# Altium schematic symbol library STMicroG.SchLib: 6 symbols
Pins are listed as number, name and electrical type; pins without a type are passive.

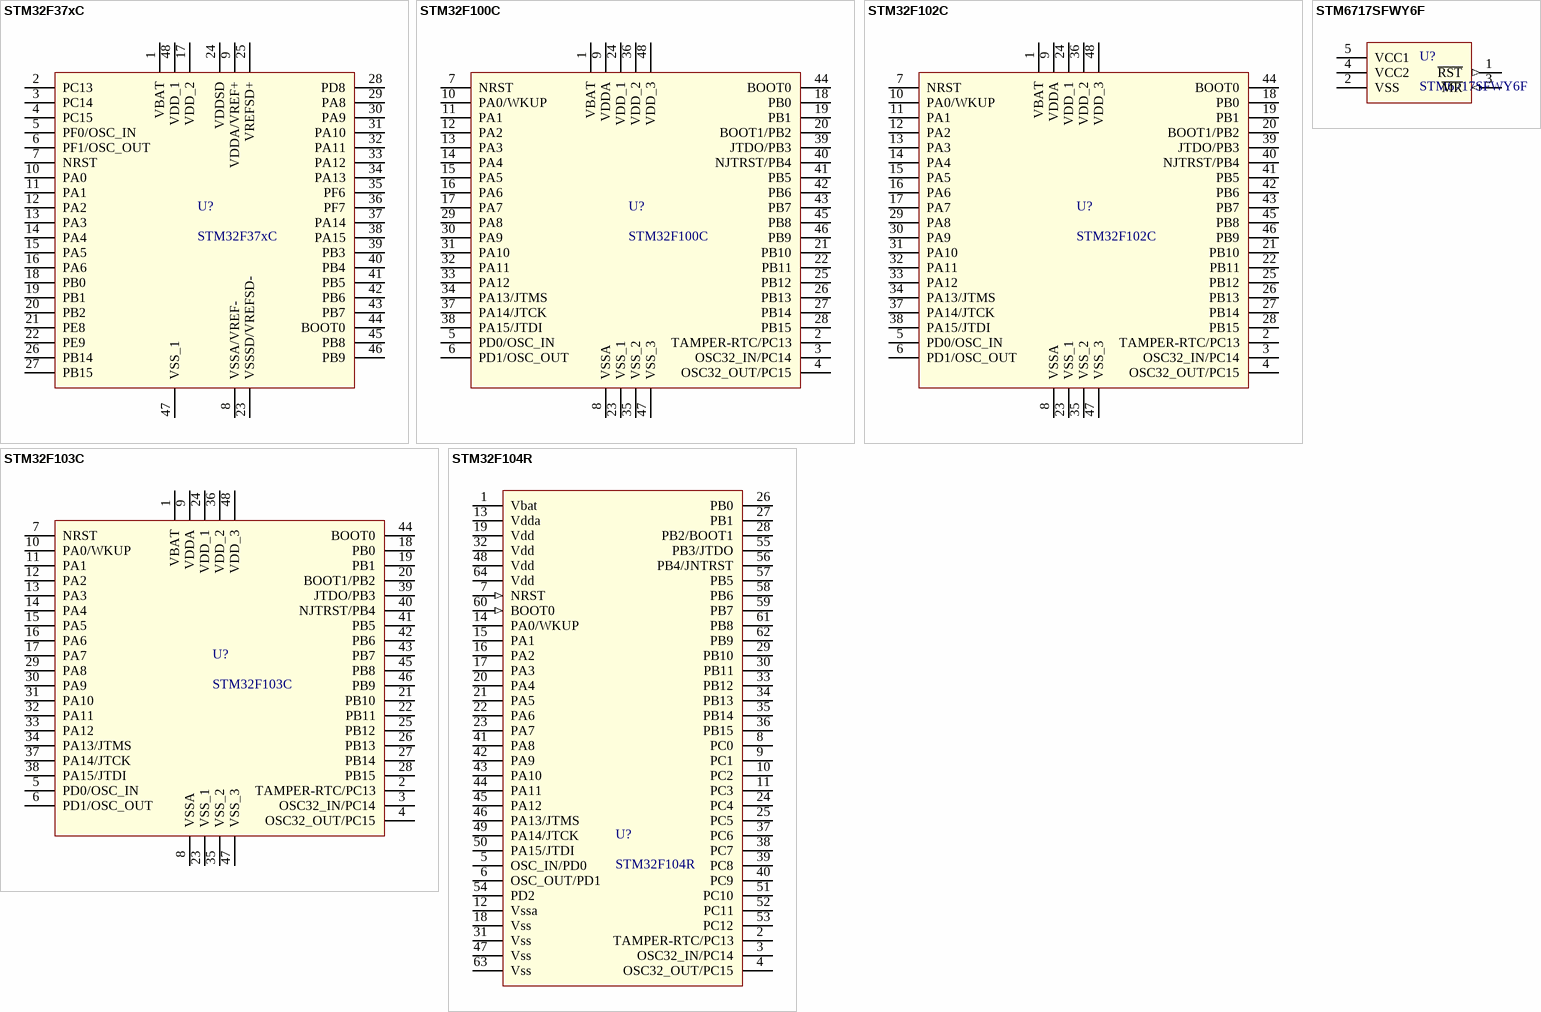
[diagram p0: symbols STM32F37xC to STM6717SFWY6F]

## STM32F37xC
designator U?
footprint SQFP50P900X900-48N (Shrink QFP, 48-Leads, Body 7x7mm, Pitch 0.5mm, IPC Medium Density)
pins: 1 VBAT, 2 PC13, 3 PC14, 4 PC15, 5 PF0/OSC_IN, 6 PF1/OSC_OUT, 7 NRST, 8 VSSA/VREF-, 9 VDDA/VREF+, 10 PA0, 11 PA1, 12 PA2, 13 PA3, 14 PA4, 15 PA5, 16 PA6, 17 VDD_2, 18 PB0, 19 PB1, 20 PB2, 21 PE8, 22 PE9, 23 VSSSD/VREFSD-, 24 VDDSD, 25 VREFSD+, 26 PB14, 27 PB15, 28 PD8, 29 PA8, 30 PA9, 31 PA10, 32 PA11, 33 PA12, 34 PA13, 35 PF6, 36 PF7, 37 PA14, 38 PA15, 39 PB3, 40 PB4, 41 PB5, 42 PB6, 43 PB7, 44 BOOT0, 45 PB8, 46 PB9, 47 VSS_1, 48 VDD_1

## STM32F100C
designator U?
footprint SQFP50P900X900-48N (Shrink QFP, 48-Leads, Body 7x7mm, Pitch 0.5mm, IPC Medium Density)
pins: 1 VBAT, 2 TAMPER-RTC/PC13, 3 OSC32_IN/PC14, 4 OSC32_OUT/PC15, 5 PD0/OSC_IN, 6 PD1/OSC_OUT, 7 NRST, 8 VSSA, 9 VDDA, 10 PA0/WKUP, 11 PA1, 12 PA2, 13 PA3, 14 PA4, 15 PA5, 16 PA6, 17 PA7, 18 PB0, 19 PB1, 20 BOOT1/PB2, 21 PB10, 22 PB11, 23 VSS_1, 24 VDD_1, 25 PB12, 26 PB13, 27 PB14, 28 PB15, 29 PA8, 30 PA9, 31 PA10, 32 PA11, 33 PA12, 34 PA13/JTMS, 35 VSS_2, 36 VDD_2, 37 PA14/JTCK, 38 PA15/JTDI, 39 JTDO/PB3, 40 NJTRST/PB4, 41 PB5, 42 PB6, 43 PB7, 44 BOOT0, 45 PB8, 46 PB9, 47 VSS_3, 48 VDD_3

## STM32F102C
designator U?
footprint SQFP50P900X900-48N (Shrink QFP, 48-Leads, Body 7x7mm, Pitch 0.5mm, IPC Medium Density)
pins: 1 VBAT, 2 TAMPER-RTC/PC13, 3 OSC32_IN/PC14, 4 OSC32_OUT/PC15, 5 PD0/OSC_IN, 6 PD1/OSC_OUT, 7 NRST, 8 VSSA, 9 VDDA, 10 PA0/WKUP, 11 PA1, 12 PA2, 13 PA3, 14 PA4, 15 PA5, 16 PA6, 17 PA7, 18 PB0, 19 PB1, 20 BOOT1/PB2, 21 PB10, 22 PB11, 23 VSS_1, 24 VDD_1, 25 PB12, 26 PB13, 27 PB14, 28 PB15, 29 PA8, 30 PA9, 31 PA10, 32 PA11, 33 PA12, 34 PA13/JTMS, 35 VSS_2, 36 VDD_2, 37 PA14/JTCK, 38 PA15/JTDI, 39 JTDO/PB3, 40 NJTRST/PB4, 41 PB5, 42 PB6, 43 PB7, 44 BOOT0, 45 PB8, 46 PB9, 47 VSS_3, 48 VDD_3

## STM32F103C
designator U?
footprint SQFP50P900X900-48N (Shrink QFP, 48-Leads, Body 7x7mm, Pitch 0.5mm, IPC Medium Density)
pins: 1 VBAT, 2 TAMPER-RTC/PC13, 3 OSC32_IN/PC14, 4 OSC32_OUT/PC15, 5 PD0/OSC_IN, 6 PD1/OSC_OUT, 7 NRST, 8 VSSA, 9 VDDA, 10 PA0/WKUP, 11 PA1, 12 PA2, 13 PA3, 14 PA4, 15 PA5, 16 PA6, 17 PA7, 18 PB0, 19 PB1, 20 BOOT1/PB2, 21 PB10, 22 PB11, 23 VSS_1, 24 VDD_1, 25 PB12, 26 PB13, 27 PB14, 28 PB15, 29 PA8, 30 PA9, 31 PA10, 32 PA11, 33 PA12, 34 PA13/JTMS, 35 VSS_2, 36 VDD_2, 37 PA14/JTCK, 38 PA15/JTDI, 39 JTDO/PB3, 40 NJTRST/PB4, 41 PB5, 42 PB6, 43 PB7, 44 BOOT0, 45 PB8, 46 PB9, 47 VSS_3, 48 VDD_3

## STM32F104R
designator U?
footprint SQFP50P1200X1200-64N (Shrink QFP, 64-Leads, Body 10x10mm, Pitch 0.5mm, IPC Medium Density)
pins: 1 Vbat (power), 2 TAMPER-RTC/PC13, 3 OSC32_IN/PC14, 4 OSC32_OUT/PC15, 5 OSC_IN/PD0, 6 OSC_OUT/PD1, 7 NRST (in), 8 PC0, 9 PC1, 10 PC2, 11 PC3, 12 Vssa (power), 13 Vdda (power), 14 PA0/WKUP, 15 PA1, 16 PA2, 17 PA3, 18 Vss (power), 19 Vdd (power), 20 PA4, 21 PA5, 22 PA6, 23 PA7, 24 PC4, 25 PC5, 26 PB0, 27 PB1, 28 PB2/BOOT1, 29 PB10, 30 PB11, 31 Vss (power), 32 Vdd (power), 33 PB12, 34 PB13, 35 PB14, 36 PB15, 37 PC6, 38 PC7, 39 PC8, 40 PC9, 41 PA8, 42 PA9, 43 PA10, 44 PA11, 45 PA12, 46 PA13/JTMS, 47 Vss (power), 48 Vdd (power), 49 PA14/JTCK, 50 PA15/JTDI, 51 PC10, 52 PC11, 53 PC12, 54 PD2, 55 PB3/JTDO, 56 PB4/JNTRST, 57 PB5, 58 PB6, 59 PB7, 60 BOOT0 (in), 61 PB8, 62 PB9, 63 Vss (power), 64 Vdd (power)

## STM6717SFWY6F
designator U?
Dual voltage supervisor with reset
pins: 1 ~{RST} (out), 2 VSS (power), 3 ~{MR} (in), 4 VCC2 (power), 5 VCC1 (power)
